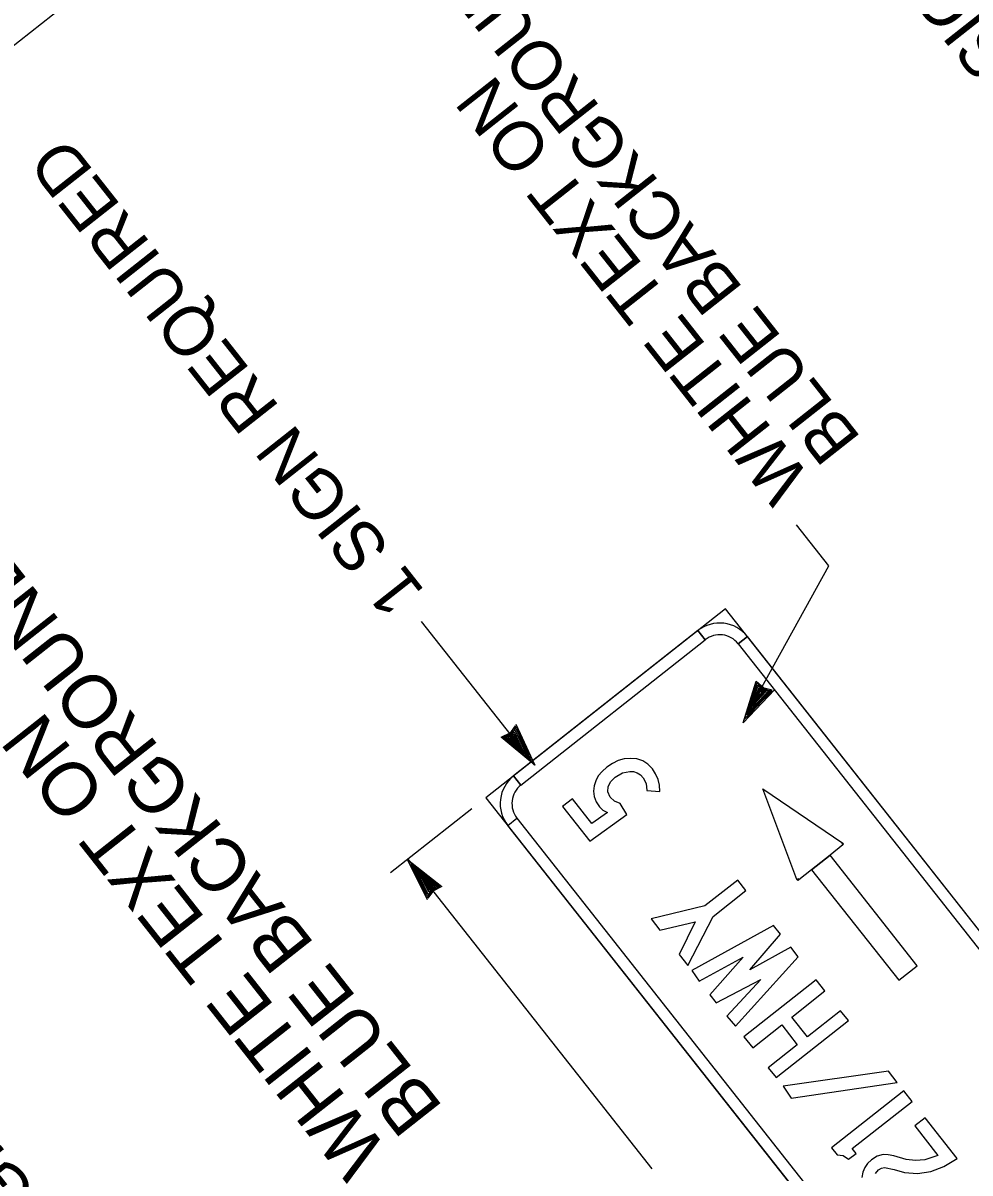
# Model space of a CAD drawing. Extents: x 672239 to 673995, y 1673540 to 1675195.
# Drawn here: x 672345.2 to 672425.9, y 1674947.8 to 1675045.8 of the extents above; entities that cross this region are included whole.
import ezdxf

# ---------------------------------------------------------------- set-up
doc = ezdxf.new("R2010")
doc.units = 0
doc.layers.add('C-ALGN-SYMB', color=7, linetype='Continuous')
doc.layers.add('C-ANNO-SYMB', color=7, linetype='Continuous')

msp = doc.modelspace()

# ---------------------------------------------------------------- linework, layer by layer
at = {"layer": 'C-ALGN-SYMB'}
for p, q in [((672239.382, 1674961.118), (672535.499, 1675194.562)), ((672388.858, 1674982.591), (672379.2, 1674994.842)), ((672406.613, 1674986.205), (672407.73, 1674989.755)), ((672406.731, 1674986.504), (672407.767, 1674989.61)), ((672406.96, 1674986.887), (672407.825, 1674989.452)), ((672407.128, 1674987.059), (672407.96, 1674989.22)), ((672407.15, 1674987.2), (672407.874, 1674989.33)), ((672407.73, 1674989.755), (672408.37, 1674989.188)), ((672407.767, 1674989.61), (672408.288, 1674989.205)), ((672407.825, 1674989.452), (672408.047, 1674989.259)), ((672407.874, 1674989.33), (672408.76, 1674988.924)), ((672407.96, 1674989.22), (672408.572, 1674988.914)), ((672408.047, 1674989.259), (672408.76, 1674988.924)), ((672408.288, 1674989.205), (672409.084, 1674989.006)), ((672408.37, 1674989.188), (672408.707, 1674988.986)), ((672409.268, 1674989.004), (672406.613, 1674986.205)), ((672408.899, 1674988.9), (672406.759, 1674986.548)), ((672409.068, 1674988.924), (672406.876, 1674986.692)), ((672408.76, 1674988.924), (672407.128, 1674987.059)), ((672408.76, 1674988.924), (672407.15, 1674987.2)), ((672407.433, 1674987.673), (672407.961, 1674989.065)), ((672408.572, 1674988.914), (672407.433, 1674987.673)), ((672407.812, 1674988.209), (672407.612, 1674988.024)), ((672407.697, 1674988.064), (672407.973, 1674988.934)), ((672408.406, 1674988.892), (672407.697, 1674988.064)), ((672408.011, 1674989.098), (672407.812, 1674988.209)), ((672408.288, 1674988.899), (672407.903, 1674988.46)), ((672407.903, 1674988.46), (672408.029, 1674988.873)), ((672407.961, 1674989.065), (672408.406, 1674988.892)), ((672407.973, 1674988.934), (672408.288, 1674988.899)), ((672408.459, 1674988.981), (672408.011, 1674989.098)), ((672408.029, 1674988.873), (672408.129, 1674988.842)), ((672408.129, 1674988.842), (672408.459, 1674988.981)), ((672408.707, 1674988.986), (672409.068, 1674988.924)), ((672408.857, 1674988.986), (672408.899, 1674988.9)), ((672406.942, 1674986.65), (672407.535, 1674987.335)), ((672407.535, 1674987.335), (672406.96, 1674986.887)), ((672407.612, 1674988.024), (672407.4, 1674987.569)), ((672407.4, 1674987.569), (672407.731, 1674987.92)), ((672385.998, 1674984.972), (672386.766, 1674985.348)), ((672386.146, 1674984.951), (672386.719, 1674985.28)), ((672386.446, 1674984.943), (672387.159, 1674985.609)), ((672386.578, 1674985.077), (672387.159, 1674985.609)), ((672386.581, 1674984.982), (672387.096, 1674985.432)), ((672386.991, 1674985.352), (672386.712, 1674984.982)), ((672386.719, 1674985.28), (672387.206, 1674985.94)), ((672386.724, 1674984.923), (672387.053, 1674985.27)), ((672386.766, 1674985.348), (672387.081, 1674985.583)), ((672386.995, 1674984.995), (672386.991, 1674985.352)), ((672387.053, 1674985.27), (672387.55, 1674984.299)), ((672387.081, 1674985.583), (672387.275, 1674985.894)), ((672387.096, 1674985.432), (672387.811, 1674983.906)), ((672387.206, 1674985.94), (672387.138, 1674985.723)), ((672387.138, 1674985.723), (672387.233, 1674985.729)), ((672387.159, 1674985.609), (672388.141, 1674983.466)), ((672387.159, 1674985.609), (672388.263, 1674983.391)), ((672387.227, 1674986.087), (672388.858, 1674982.591)), ((672387.233, 1674985.729), (672388.596, 1674982.856)), ((672387.275, 1674985.894), (672388.507, 1674983.019)), ((672388.858, 1674982.591), (672385.998, 1674984.972)), ((672388.627, 1674982.814), (672386.146, 1674984.951)), ((672386.315, 1674984.944), (672386.578, 1674985.077)), ((672388.359, 1674983.171), (672386.315, 1674984.944)), ((672388.141, 1674983.466), (672386.446, 1674984.943)), ((672388.263, 1674983.391), (672386.581, 1674984.982)), ((672386.712, 1674984.982), (672387.46, 1674984.461)), ((672387.811, 1674983.906), (672386.724, 1674984.923)), ((672386.85, 1674984.886), (672387.002, 1674985.164)), ((672387.55, 1674984.299), (672386.85, 1674984.886)), ((672386.928, 1674984.914), (672386.995, 1674984.995)), ((672387.262, 1674984.641), (672386.928, 1674984.914)), ((672387.002, 1674985.164), (672387.262, 1674984.641)), ((672387.46, 1674984.461), (672387.555, 1674984.205)), ((672383.474, 1674978.876), (672376.57, 1674973.433)), ((672379.718, 1674971.11), (672378.014, 1674974.571)), ((672378.014, 1674974.571), (672380.923, 1674972.25)), ((672398.862, 1674948.195), (672378.048, 1674974.598)), ((672378.374, 1674974.151), (672378.25, 1674974.354)), ((672378.25, 1674974.354), (672380.774, 1674972.268)), ((672379.704, 1674971.468), (672378.282, 1674974.311)), ((672378.282, 1674974.311), (672378.311, 1674974.104)), ((672378.311, 1674974.104), (672378.736, 1674973.305)), ((672379.665, 1674971.302), (672378.374, 1674974.151)), ((672378.736, 1674973.305), (672378.526, 1674974.002)), ((672378.526, 1674974.002), (672380.606, 1674972.271)), ((672379.776, 1674971.589), (672378.625, 1674973.783)), ((672378.625, 1674973.783), (672380.34, 1674972.228)), ((672379.776, 1674971.589), (672378.749, 1674973.712)), ((672378.749, 1674973.712), (672380.474, 1674972.269)), ((672379.35, 1674972.984), (672379.003, 1674973.346)), ((672379.003, 1674973.346), (672379.21, 1674972.91)), ((672379.834, 1674971.768), (672379.088, 1674973.278)), ((672379.088, 1674973.278), (672380.196, 1674972.283)), ((672379.451, 1674972.731), (672379.35, 1674972.984)), ((672379.874, 1674971.93), (672379.357, 1674972.891)), ((672379.357, 1674972.891), (672380.069, 1674972.319)), ((672380.209, 1674972.225), (672379.451, 1674972.731)), ((672379.923, 1674972.038), (672379.653, 1674972.555)), ((672379.653, 1674972.555), (672379.992, 1674972.289)), ((672379.853, 1674971.616), (672379.665, 1674971.302)), ((672380.209, 1674971.927), (672379.736, 1674971.257)), ((672380.474, 1674972.269), (672379.776, 1674971.589)), ((672380.346, 1674972.133), (672379.776, 1674971.589)), ((672380.34, 1674972.228), (672379.834, 1674971.768)), ((672380.163, 1674971.858), (672379.853, 1674971.616)), ((672380.196, 1674972.283), (672379.874, 1674971.93)), ((672380.069, 1674972.319), (672379.923, 1674972.038)), ((672379.992, 1674972.289), (672379.927, 1674972.207)), ((672379.927, 1674972.207), (672379.938, 1674971.849)), ((672379.938, 1674971.849), (672380.209, 1674972.225)), ((672380.923, 1674972.25), (672380.163, 1674971.858)), ((672380.774, 1674972.268), (672380.209, 1674971.927)), ((672380.606, 1674972.271), (672380.346, 1674972.133)), ((672379.799, 1674971.476), (672379.704, 1674971.468))]:
    msp.add_line(p, q, dxfattribs=at)
msp.add_lwpolyline([(672407.751, 1674988.413), (672413.913, 1674999.589), (672411.167, 1675003.072)], dxfattribs=at)
at = {"layer": 'C-ANNO-SYMB'}
for p, q in [((672405.109, 1674995.922), (672384.691, 1674979.825)), ((672457.114, 1674929.956), (672405.109, 1674995.922)), ((672402.754, 1674994.065), (672387.047, 1674981.683)), ((672387.666, 1674980.897), (672403.373, 1674993.279)), ((672402.754, 1674994.065), (672403.373, 1674993.279)), ((672403.373, 1674993.279), (672402.754, 1674994.065)), ((672403.373, 1674993.279), (672402.754, 1674994.065)), ((672403.373, 1674993.279), (672403.373, 1674993.279)), ((672403.373, 1674993.279), (672403.373, 1674993.279)), ((672406.181, 1674992.947), (672406.967, 1674993.566)), ((672406.967, 1674993.566), (672406.181, 1674992.947)), ((672455.257, 1674932.312), (672406.967, 1674993.566)), ((672406.181, 1674992.947), (672454.471, 1674931.693)), ((672387.666, 1674980.897), (672387.047, 1674981.683)), ((672387.047, 1674981.683), (672387.666, 1674980.897)), ((672408.28, 1674980.594), (672408.28, 1674980.594)), ((672408.28, 1674980.594), (672408.28, 1674980.594)), ((672411.193, 1674972.868), (672408.28, 1674980.594)), ((672408.28, 1674980.594), (672415.112, 1674975.958)), ((672384.691, 1674979.825), (672436.696, 1674913.859)), ((672386.549, 1674977.469), (672387.334, 1674978.088)), ((672386.549, 1674977.469), (672387.334, 1674978.088)), ((672434.839, 1674916.215), (672386.549, 1674977.469)), ((672387.334, 1674978.088), (672387.334, 1674978.088)), ((672387.334, 1674978.088), (672387.334, 1674978.088)), ((672387.334, 1674978.088), (672435.624, 1674916.834)), ((672415.117, 1674975.797), (672414.018, 1674974.93)), ((672415.112, 1674975.958), (672415.055, 1674975.876)), ((672415.055, 1674975.876), (672415.112, 1674975.958)), ((672415.055, 1674975.876), (672415.117, 1674975.797)), ((672415.117, 1674975.797), (672415.055, 1674975.876)), ((672412.447, 1674973.692), (672414.018, 1674974.93)), ((672412.447, 1674973.692), (672414.018, 1674974.93)), ((672414.018, 1674974.93), (672412.447, 1674973.692)), ((672421.447, 1674965.507), (672414.018, 1674974.93)), ((672412.447, 1674973.692), (672411.348, 1674972.826)), ((672412.447, 1674973.692), (672419.876, 1674964.269)), ((672411.286, 1674972.904), (672411.193, 1674972.868)), ((672411.193, 1674972.868), (672411.286, 1674972.904)), ((672411.348, 1674972.826), (672411.286, 1674972.904)), ((672411.286, 1674972.904), (672411.348, 1674972.826)), ((672419.876, 1674964.269), (672421.447, 1674965.507)), ((672421.447, 1674965.507), (672421.447, 1674965.507)), ((672421.447, 1674965.507), (672421.447, 1674965.507))]:
    msp.add_line(p, q, dxfattribs=at)
for points in [[(672399.505, 1674980.349), (672399.471, 1674980.888), (672399.353, 1674981.388), (672399.153, 1674981.85), (672398.871, 1674982.277), (672398.485, 1674982.676), (672398.046, 1674982.96), (672397.552, 1674983.128), (672397.001, 1674983.18), (672396.476, 1674983.13), (672395.965, 1674982.987), (672395.468, 1674982.752), (672394.98, 1674982.422), (672394.582, 1674982.063), (672394.267, 1674981.676), (672394.041, 1674981.269), (672393.901, 1674980.837), (672393.859, 1674980.369), (672393.921, 1674979.916), (672394.094, 1674979.47), (672394.371, 1674979.041), (672394.659, 1674978.778), (672395.057, 1674978.575), (672393.72, 1674977.63), (672392.064, 1674979.731), (672391.218, 1674979.065), (672393.53, 1674976.131), (672396.693, 1674978.382), (672396.131, 1674979.32), (672395.658, 1674979.529), (672395.289, 1674979.865), (672395.075, 1674980.314), (672395.111, 1674980.793), (672395.334, 1674981.202), (672395.713, 1674981.58), (672396.317, 1674981.937), (672396.938, 1674982.071), (672397.277, 1674982.048), (672397.581, 1674981.947), (672397.857, 1674981.771), (672398.099, 1674981.518), (672398.345, 1674981.031), (672398.397, 1674980.433)], [(672399.516, 1674968.539), (672402.516, 1674969.241), (672401.149, 1674966.467), (672401.892, 1674965.524), (672404.052, 1674969.715), (672406.844, 1674971.916), (672406.143, 1674972.805), (672403.352, 1674970.604), (672398.757, 1674969.501)], [(672411.307, 1674966.254), (672410.659, 1674967.077), (672407.189, 1674965.163), (672409.783, 1674968.188), (672409.183, 1674968.949), (672402.232, 1674965.094), (672402.866, 1674964.186), (672406.608, 1674966.248), (672403.768, 1674963.041), (672404.315, 1674962.347), (672408.111, 1674964.341), (672405.213, 1674961.208), (672405.954, 1674960.373)], [(672415.582, 1674960.832), (672414.916, 1674961.677), (672412.088, 1674959.448), (672410.754, 1674961.14), (672413.582, 1674963.369), (672412.84, 1674964.311), (672406.678, 1674959.453), (672407.421, 1674958.512), (672409.892, 1674960.46), (672411.225, 1674958.768), (672408.754, 1674956.82), (672409.421, 1674955.975)], [(672419.742, 1674955.555), (672418.988, 1674956.512), (672410.005, 1674955.234), (672410.709, 1674954.237)], [(672421.009, 1674953.948), (672420.299, 1674954.848), (672414.138, 1674949.991), (672414.608, 1674949.395), (672415.131, 1674949.353), (672415.582, 1674949.015), (672416.227, 1674949.523), (672415.909, 1674949.927)]]:
    msp.add_lwpolyline(points, close=True, dxfattribs=at)
msp.add_lwpolyline([(672417.886, 1674947.795), (672418.15, 1674948.116), (672418.386, 1674948.253), (672418.643, 1674948.312), (672419.472, 1674948.14), (672420.362, 1674947.882), (672421.474, 1674947.795), (672422.591, 1674947.966), (672423.715, 1674948.395), (672424.844, 1674949.084), (672422.11, 1674952.551), (672421.229, 1674951.856), (672423.208, 1674949.346), (672422.104, 1674948.969), (672421.306, 1674948.909), (672420.499, 1674949.013), (672419.45, 1674949.31), (672418.955, 1674949.409), (672418.53, 1674949.414), (672418.034, 1674949.27), (672417.535, 1674948.963), (672417.214, 1674948.655), (672416.971, 1674948.304), (672416.81, 1674947.911), (672416.727, 1674947.475)], dxfattribs=at)
for centre, radius, start, end in [((672404.611, 1674991.709), 3, 38.2506, 128.25081), ((672404.611, 1674991.709), 2, 38.2506, 128.25081), ((672388.905, 1674979.327), 3, 128.25054, 218.25075), ((672388.905, 1674979.327), 2, 128.25054, 218.25075), ((672415.055, 1674975.876), 0.1, 308.25039, 55.35339), ((672411.286, 1674972.904), 0.1, 201.14796, 308.25039)]:
    msp.add_arc(centre, radius, start, end, dxfattribs=at)

# ---------------------------------------------------------------- texts
at = {"layer": 'C-ALGN-SYMB'}
for s, height, p in [('1 SIGN REQUIRED', 4.2, (672432.919, 1675039.449)), ('BLUE BACKGROUND', 4.2, (672416.741, 1675010.427)), ('WHITE TEXT ON', 4.2, (672412.447, 1675007.042)), ('1 SIGN REQUIRED', 4.2, (672379.557, 1674997.381)), ('BLUE BACKGROUND', 4.57469, (672381.123, 1674953.409)), ('WHITE TEXT ON', 4.57469, (672376.446, 1674949.722)), ('2 SIGNS REQUIRED', 4.2, (672352.794, 1674938.234))]:
    msp.add_text(s, height=height, rotation=128.25054, dxfattribs=at).set_placement(p)

doc.saveas('drawing.dxf')
